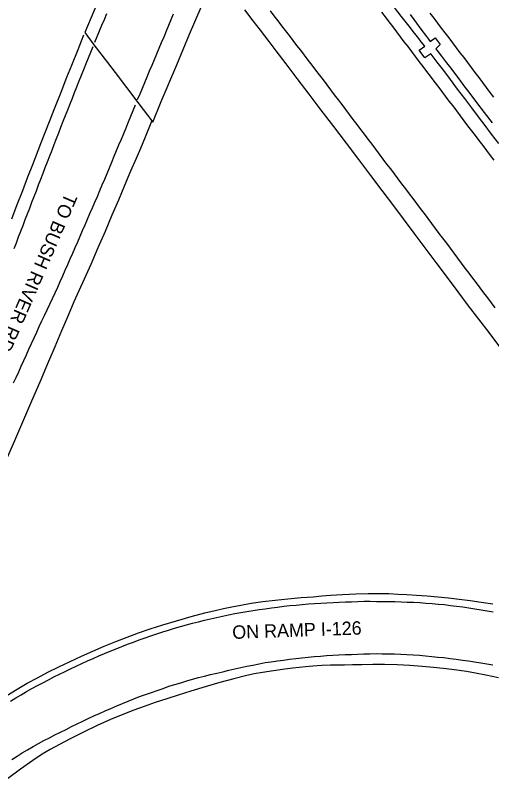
# Model space of a CAD drawing. Extents: x 1948091 to 1975253, y 787267 to 823306.
# Drawn here: x 1969225.2 to 1969417.4, y 798049 to 798356.6 of the extents above; entities that cross this region are included whole.
import ezdxf

# ---------------------------------------------------------------- set-up
doc = ezdxf.new("R2010")
doc.units = 0
for name, color, linetype in [('RD_EX_Bridge', 7, 'Continuous'), ('RD_EX_Pavement_Markings', 7, 'Continuous'), ('RD_EX_Road', 7, 'Continuous'), ('RD_TX_RoadID', 7, 'Continuous')]:
    doc.layers.add(name, color=color, linetype=linetype)

msp = doc.modelspace()

# ---------------------------------------------------------------- linework, layer by layer
at = {"layer": 'RD_EX_Bridge'}
for points in [[(1969260.48, 798367.01), (1969253.24, 798349.63)], [(1969253.24, 798349.63), (1969256.94, 798344.75), (1969262.39, 798337.57), (1969265.47, 798333.55), (1969270.04, 798327.58), (1969274.66, 798321.46), (1969280.69, 798313.53), (1969284.08, 798321.89), (1969290.35, 798336.69), (1969295.54, 798349.06), (1969300.17, 798359.88)]]:
    msp.add_lwpolyline(points, dxfattribs=at)
at = {"layer": 'RD_EX_Pavement_Markings'}
for points in [[(1969257.29, 798345.75), (1969258.26, 798348.06), (1969259.22, 798350.36), (1969260.19, 798352.67), (1969261.15, 798354.98), (1969262.12, 798357.28)], [(1969274.56, 798322.65), (1969275.53, 798324.95), (1969276.5, 798327.26), (1969277.47, 798329.56), (1969278.44, 798331.87), (1969279.41, 798334.17), (1969280.38, 798336.47), (1969281.34, 798338.78), (1969282.31, 798341.08), (1969283.28, 798343.39), (1969284.25, 798345.69), (1969285.22, 798347.99), (1969286.19, 798350.3), (1969287.15, 798352.6), (1969288.12, 798354.91), (1969289.09, 798357.21)], [(1969328.02, 798358.36), (1969329.55, 798356.37), (1969331.07, 798354.39), (1969332.59, 798352.41), (1969334.12, 798350.43), (1969335.64, 798348.44), (1969337.16, 798346.46), (1969338.69, 798344.48), (1969340.21, 798342.5), (1969341.73, 798340.52), (1969343.26, 798338.53), (1969344.78, 798336.55), (1969346.3, 798334.57), (1969347.81, 798332.58), (1969349.32, 798330.58), (1969350.83, 798328.59), (1969352.34, 798326.6), (1969353.85, 798324.61), (1969355.36, 798322.61), (1969356.87, 798320.62), (1969358.38, 798318.63), (1969359.89, 798316.64), (1969361.4, 798314.64), (1969362.91, 798312.65), (1969364.42, 798310.66), (1969365.93, 798308.66), (1969367.44, 798306.67), (1969368.95, 798304.68), (1969370.45, 798302.69), (1969371.96, 798300.69), (1969373.47, 798298.7), (1969374.98, 798296.7), (1969376.49, 798294.71), (1969378, 798292.72), (1969379.5, 798290.72), (1969381.01, 798288.73), (1969382.52, 798286.74), (1969384.03, 798284.74), (1969385.54, 798282.75), (1969387.05, 798280.76), (1969388.55, 798278.76), (1969390.06, 798276.77), (1969391.56, 798274.77), (1969393.06, 798272.77), (1969394.56, 798270.77), (1969396.05, 798268.76), (1969397.55, 798266.76), (1969399.05, 798264.76), (1969400.55, 798262.76), (1969402.05, 798260.76), (1969403.54, 798258.76), (1969405.04, 798256.75), (1969406.55, 798254.76), (1969408.05, 798252.76), (1969409.56, 798250.77), (1969411.07, 798248.77), (1969412.57, 798246.78), (1969414.08, 798244.78), (1969415.59, 798242.79), (1969417.09, 798240.79), (1969418.6, 798238.8)], [(1969372.9, 798357.93), (1969374.41, 798355.94), (1969375.92, 798353.94), (1969377.43, 798351.95), (1969378.94, 798349.96), (1969380.45, 798347.97), (1969381.96, 798345.98), (1969383.48, 798343.98), (1969384.99, 798341.99), (1969386.5, 798340), (1969388.01, 798338.01), (1969389.52, 798336.02), (1969391.03, 798334.02), (1969392.54, 798332.03), (1969394.05, 798330.04), (1969395.56, 798328.05), (1969397.07, 798326.06), (1969398.58, 798324.06), (1969400.09, 798322.07), (1969401.6, 798320.08), (1969403.11, 798318.09), (1969404.62, 798316.09), (1969406.13, 798314.1), (1969407.64, 798312.11), (1969409.16, 798310.12), (1969410.67, 798308.13), (1969412.18, 798306.14), (1969413.7, 798304.15), (1969415.21, 798302.16), (1969416.72, 798300.17), (1969418.24, 798298.18)], [(1969392.42, 798357.44), (1969393.94, 798355.45), (1969395.46, 798353.46), (1969396.97, 798351.47), (1969398.49, 798349.48), (1969400, 798347.49), (1969401.52, 798345.51), (1969403.03, 798343.52), (1969404.55, 798341.53), (1969406.06, 798339.54), (1969407.57, 798337.55), (1969409.08, 798335.55), (1969410.58, 798333.55), (1969412.08, 798331.56), (1969413.59, 798329.56), (1969415.09, 798327.56), (1969416.6, 798325.57), (1969418.1, 798323.57)], [(1969256.52, 798343.94), (1969255.58, 798341.62), (1969254.65, 798339.31), (1969253.71, 798336.99), (1969252.78, 798334.67), (1969251.84, 798332.35), (1969250.91, 798330.04), (1969249.98, 798327.72), (1969249.04, 798325.4), (1969248.11, 798323.08), (1969247.17, 798320.76), (1969246.24, 798318.45), (1969245.31, 798316.12), (1969244.41, 798313.79), (1969243.51, 798311.46), (1969242.61, 798309.13), (1969241.71, 798306.8), (1969240.81, 798304.47), (1969239.91, 798302.13), (1969239.01, 798299.8), (1969238.11, 798297.47), (1969237.21, 798295.14), (1969236.31, 798292.81), (1969235.41, 798290.48), (1969234.51, 798288.15), (1969233.62, 798285.81), (1969232.72, 798283.48), (1969231.82, 798281.15), (1969230.93, 798278.82), (1969230.03, 798276.48), (1969229.13, 798274.15), (1969228.24, 798271.82), (1969227.34, 798269.49), (1969226.44, 798267.16), (1969225.55, 798264.82), (1969224.65, 798262.49)], [(1969273.6, 798320.44), (1969272.64, 798318.13), (1969271.69, 798315.82), (1969270.73, 798313.51), (1969269.78, 798311.2), (1969268.82, 798308.9), (1969267.87, 798306.59), (1969266.91, 798304.28), (1969265.96, 798301.97), (1969265, 798299.66), (1969264.05, 798297.35), (1969263.09, 798295.04), (1969262.14, 798292.73), (1969261.17, 798290.43), (1969260.18, 798288.13), (1969259.19, 798285.84), (1969258.2, 798283.54), (1969257.21, 798281.25), (1969256.22, 798278.95), (1969255.23, 798276.66), (1969254.24, 798274.36), (1969253.25, 798272.07), (1969252.26, 798269.78), (1969251.27, 798267.48), (1969250.26, 798265.19), (1969249.26, 798262.91), (1969248.25, 798260.62), (1969247.24, 798258.34), (1969246.23, 798256.05), (1969245.22, 798253.76), (1969244.21, 798251.48), (1969243.2, 798249.19), (1969242.2, 798246.91), (1969241.14, 798244.64), (1969240.08, 798242.38), (1969239.02, 798240.12), (1969237.97, 798237.86), (1969236.91, 798235.59), (1969235.85, 798233.33), (1969234.79, 798231.07), (1969233.73, 798228.81), (1969232.69, 798226.53), (1969231.66, 798224.26), (1969230.63, 798221.98), (1969229.6, 798219.71), (1969228.57, 798217.43), (1969227.53, 798215.16), (1969226.5, 798212.89), (1969225.47, 798210.61), (1969224.44, 798208.34)], [(1969223.36, 798080.3), (1969225.51, 798081.59), (1969227.65, 798082.87), (1969229.79, 798084.16), (1969231.97, 798085.38), (1969234.18, 798086.56), (1969236.38, 798087.74), (1969238.59, 798088.92), (1969240.79, 798090.1), (1969243.03, 798091.21), (1969245.29, 798092.29), (1969247.54, 798093.36), (1969249.8, 798094.44), (1969252.06, 798095.51), (1969254.34, 798096.53), (1969256.64, 798097.51), (1969258.94, 798098.49), (1969261.24, 798099.48), (1969263.55, 798100.43), (1969265.87, 798101.37), (1969268.18, 798102.31), (1969270.5, 798103.24), (1969272.85, 798104.1), (1969275.2, 798104.95), (1969277.55, 798105.8), (1969279.91, 798106.64), (1969282.29, 798107.4), (1969284.67, 798108.16), (1969287.05, 798108.92), (1969289.43, 798109.68), (1969291.83, 798110.37), (1969294.25, 798111.01), (1969296.66, 798111.66), (1969299.08, 798112.31), (1969301.49, 798112.96), (1969303.92, 798113.52), (1969306.37, 798114.05), (1969308.81, 798114.59), (1969311.26, 798115.09), (1969313.71, 798115.56), (1969316.16, 798116.03), (1969318.63, 798116.42), (1969321.1, 798116.8), (1969323.57, 798117.17), (1969326.04, 798117.53), (1969328.52, 798117.87), (1969330.99, 798118.2), (1969333.47, 798118.54), (1969335.95, 798118.79), (1969338.44, 798119.01), (1969340.93, 798119.22), (1969343.41, 798119.44), (1969345.9, 798119.61), (1969348.4, 798119.75), (1969350.89, 798119.89), (1969353.38, 798120.03), (1969355.87, 798120.17), (1969358.37, 798120.26), (1969360.86, 798120.35), (1969363.36, 798120.43), (1969365.85, 798120.52), (1969368.34, 798120.52), (1969370.84, 798120.5), (1969373.34, 798120.49), (1969375.83, 798120.48), (1969378.32, 798120.43), (1969380.82, 798120.32), (1969383.31, 798120.22), (1969385.8, 798120.12), (1969388.29, 798120), (1969390.78, 798119.8), (1969393.27, 798119.59), (1969395.75, 798119.39), (1969398.24, 798119.18), (1969400.72, 798118.9), (1969403.19, 798118.6), (1969405.67, 798118.3), (1969408.13, 798117.9), (1969410.59, 798117.49), (1969413.05, 798117.08), (1969415.51, 798116.67), (1969417.97, 798116.25)], [(1969223.89, 798056.76), (1969225.96, 798058.15), (1969228.06, 798059.52), (1969230.23, 798060.75), (1969232.4, 798061.99), (1969234.58, 798063.23), (1969236.79, 798064.38), (1969239.01, 798065.53), (1969241.23, 798066.68), (1969243.45, 798067.83), (1969245.7, 798068.93), (1969247.94, 798070.03), (1969250.18, 798071.14), (1969252.43, 798072.24), (1969254.69, 798073.31), (1969256.97, 798074.33), (1969259.25, 798075.35), (1969261.53, 798076.37), (1969263.81, 798077.4), (1969266.12, 798078.36), (1969268.44, 798079.3), (1969270.75, 798080.24), (1969273.07, 798081.18), (1969275.39, 798082.12), (1969277.74, 798082.96), (1969280.1, 798083.79), (1969282.45, 798084.62), (1969284.81, 798085.46), (1969287.17, 798086.27), (1969289.57, 798086.99), (1969291.96, 798087.71), (1969294.36, 798088.42), (1969296.75, 798089.14), (1969299.17, 798089.77), (1969301.59, 798090.38), (1969304.01, 798090.99), (1969306.44, 798091.61), (1969308.87, 798092.17), (1969311.31, 798092.72), (1969313.74, 798093.28), (1969316.18, 798093.83), (1969318.63, 798094.34), (1969321.08, 798094.83), (1969323.52, 798095.33), (1969325.97, 798095.83), (1969328.45, 798096.17), (1969330.92, 798096.52), (1969333.39, 798096.86), (1969335.87, 798097.17), (1969338.35, 798097.48), (1969340.83, 798097.78), (1969343.31, 798098.08), (1969345.79, 798098.27), (1969348.28, 798098.46), (1969350.77, 798098.65), (1969353.26, 798098.8), (1969355.76, 798098.92), (1969358.25, 798099.04), (1969360.74, 798099.15), (1969363.24, 798099.23), (1969365.73, 798099.3), (1969368.22, 798099.37), (1969370.72, 798099.44), (1969373.21, 798099.41), (1969375.71, 798099.35), (1969378.2, 798099.3), (1969380.69, 798099.25), (1969383.18, 798099.1), (1969385.67, 798098.95), (1969388.16, 798098.79), (1969390.65, 798098.58), (1969393.13, 798098.33), (1969395.61, 798098.08), (1969398.09, 798097.82), (1969400.56, 798097.49), (1969403.03, 798097.16), (1969405.5, 798096.84), (1969407.97, 798096.49), (1969410.44, 798096.11), (1969412.9, 798095.73), (1969415.37, 798095.35), (1969417.82, 798094.9)]]:
    msp.add_lwpolyline(points, dxfattribs=at)
at = {"layer": 'RD_EX_Road'}
for points in [[(1969420.66, 798222.98), (1969416.26, 798228.76), (1969412.11, 798234.22), (1969408.01, 798239.62), (1969403.8, 798245.2), (1969399.46, 798250.99), (1969395, 798256.97), (1969390.52, 798262.98), (1969386.11, 798268.88), (1969381.77, 798274.66), (1969377.52, 798280.32), (1969373.18, 798286.07), (1969368.6, 798292.12), (1969363.79, 798298.47), (1969358.74, 798305.11), (1969353.63, 798311.84), (1969348.62, 798318.43), (1969343.72, 798324.89), (1969338.91, 798331.21), (1969334.42, 798337.12), (1969330.45, 798342.31), (1969327.58, 798346.05), (1969324.09, 798350.57), (1969321.19, 798354.34), (1969317.78, 798358.82)], [(1969420.19, 798304.93), (1969417.3, 798308.74), (1969414.69, 798312.19), (1969412.05, 798315.68), (1969409.32, 798319.3), (1969406.51, 798323.04), (1969403.61, 798326.9), (1969400.73, 798330.72), (1969398, 798334.33), (1969395.39, 798337.72), (1969392.93, 798340.91), (1969392.75, 798341.14), (1969390.4, 798339.49), (1969388.03, 798342.54), (1969390.31, 798344.22), (1969388.93, 798345.97), (1969387.91, 798347.28), (1969386.84, 798348.65), (1969385.71, 798350.08), (1969384.53, 798351.58), (1969383.02, 798353.51), (1969380.87, 798356.22), (1969378.11, 798359.74)], [(1969384.41, 798356.89), (1969385.88, 798354.9), (1969388.74, 798351.05), (1969390.98, 798348.06), (1969391.84, 798346.93), (1969392.47, 798346.1), (1969394.49, 798347.49), (1969396.51, 798344.84), (1969394.76, 798343.11), (1969395.21, 798342.52), (1969396.17, 798341.31), (1969397.08, 798340.16), (1969397.95, 798339.07), (1969398.76, 798338.04), (1969399.69, 798336.84), (1969400.89, 798335.26), (1969402.35, 798333.3), (1969404.09, 798330.95), (1969406.13, 798328.2), (1969408.51, 798325.04), (1969411.21, 798321.45), (1969414.25, 798317.46), (1969417.46, 798313.25)], [(1969252.79, 798348.55), (1969251.82, 798346.14), (1969250.42, 798342.69), (1969247.89, 798336.4), (1969245.95, 798331.51), (1969243.55, 798325.45), (1969241.07, 798319.18), (1969238.88, 798313.65), (1969235.4, 798304.81), (1969232.13, 798296.4), (1969230.21, 798291.43), (1969228.1, 798285.93), (1969225.9, 798280.2), (1969223.71, 798274.5)], [(1969280.21, 798313.79), (1969277.57, 798307.48), (1969275.67, 798302.97), (1969273.93, 798298.85), (1969271.74, 798293.75), (1969269.3, 798288.05), (1969266.81, 798282.18), (1969264.2, 798276.04), (1969261.42, 798269.54), (1969258.55, 798262.87), (1969255.66, 798256.25), (1969253.02, 798250.3), (1969250.89, 798245.63), (1969248.86, 798241.12), (1969246.51, 798235.62), (1969243.93, 798229.47), (1969241.18, 798223.02), (1969238.24, 798216.16), (1969235.08, 798208.8), (1969231.81, 798201.21), (1969228.53, 798193.63), (1969225.28, 798186.11), (1969222.07, 798178.7)], [(1969221.83, 798082.62), (1969225.98, 798085.12), (1969230.03, 798087.49), (1969234.13, 798089.75), (1969238.42, 798091.96), (1969242.85, 798094.14), (1969247.35, 798096.3), (1969251.91, 798098.43), (1969256.52, 798100.48), (1969261.13, 798102.46), (1969265.72, 798104.35), (1969270.3, 798106.13), (1969274.89, 798107.77), (1969279.64, 798109.38), (1969284.71, 798111.04), (1969290.18, 798112.72), (1969296.15, 798114.38), (1969301.67, 798115.82), (1969305.82, 798116.85), (1969309.23, 798117.64), (1969312.55, 798118.34), (1969316.15, 798119.02), (1969320.41, 798119.74), (1969325.1, 798120.43), (1969329.97, 798121.04), (1969335.08, 798121.56), (1969340.5, 798122.01), (1969345.39, 798122.38), (1969348.9, 798122.68), (1969352.39, 798122.95), (1969357.19, 798123.25), (1969362.49, 798123.5), (1969367.48, 798123.65), (1969371.99, 798123.69), (1969375.84, 798123.61), (1969379.43, 798123.46), (1969383.13, 798123.26), (1969387.04, 798123.03), (1969391.26, 798122.73), (1969395.62, 798122.36), (1969399.95, 798121.9), (1969404.28, 798121.39), (1969408.65, 798120.85), (1969413.12, 798120.23), (1969417.73, 798119.5)], [(1969420.13, 798089.74), (1969415.02, 798090.77), (1969410.77, 798091.59), (1969407.23, 798092.22), (1969404.23, 798092.68), (1969401.27, 798093.07), (1969397.82, 798093.46), (1969393.84, 798093.86), (1969389.28, 798094.25), (1969384.33, 798094.6), (1969379.21, 798094.89), (1969374.15, 798095.05), (1969369.38, 798095.05), (1969365.03, 798094.98), (1969361.23, 798094.91), (1969357.96, 798094.86), (1969355.19, 798094.81), (1969352.34, 798094.74), (1969348.8, 798094.63), (1969345.23, 798094.45), (1969342.3, 798094.19), (1969339.69, 798093.9), (1969337.09, 798093.59), (1969333.87, 798093.16), (1969329.4, 798092.5), (1969324.89, 798091.8), (1969321.51, 798091.24), (1969318.07, 798090.51), (1969313.33, 798089.29), (1969307.75, 798087.75), (1969301.79, 798086.01), (1969296.01, 798084.28), (1969290.97, 798082.74), (1969286.32, 798081.25), (1969281.7, 798079.7), (1969277.22, 798078.14), (1969272.98, 798076.64), (1969268.59, 798074.97), (1969263.64, 798072.91), (1969258.29, 798070.5), (1969252.69, 798067.82), (1969247.41, 798065.17), (1969243.02, 798062.88), (1969239.29, 798060.82), (1969236.02, 798058.88), (1969232.32, 798056.43), (1969227.32, 798052.84), (1969222.15, 798049.04)]]:
    msp.add_lwpolyline(points, dxfattribs=at)

# ---------------------------------------------------------------- texts
at = {"layer": 'RD_TX_RoadID'}
for s, rotation, p in [('TO BUSH RIVER RD', 246.5244, (1969245.43, 798285.35)), ('ON RAMP I-126', 1.9899, (1969312.82, 798105.34))]:
    msp.add_text(s, height=5.4, rotation=rotation, dxfattribs=at).set_placement(p)

doc.saveas('drawing.dxf')
